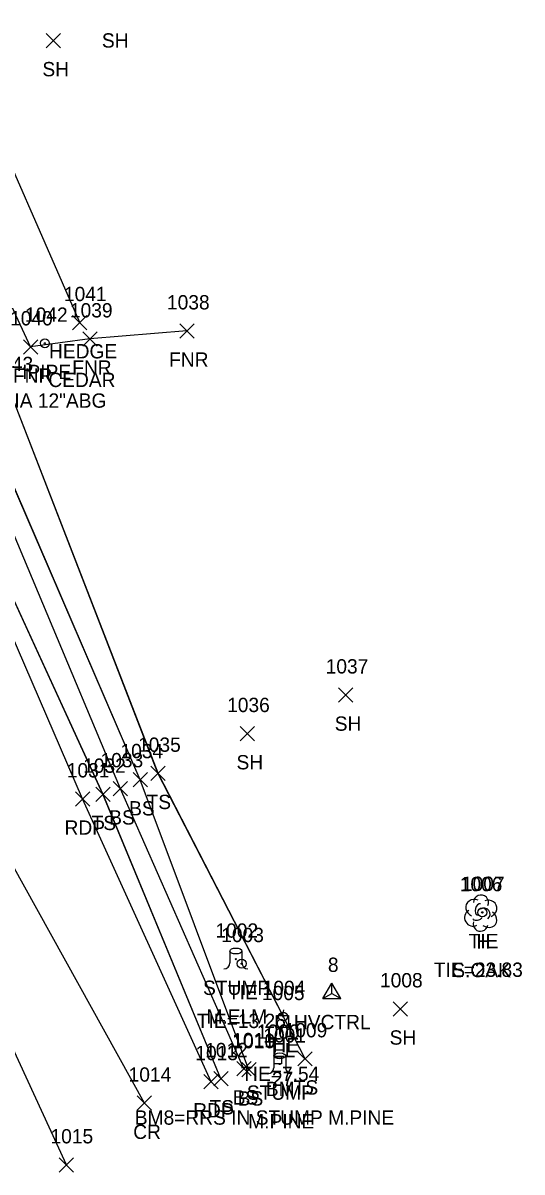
# Model space of a CAD drawing. Extents: x 1415642 to 1422021, y 544543 to 547232.
# Drawn here: x 1416593.3 to 1416662.9, y 546174.1 to 546334.5 of the extents above; entities that cross this region are included whole.
import ezdxf

# ---------------------------------------------------------------- set-up
doc = ezdxf.new("R2010")
doc.units = 0
for name, color, linetype in [('C_A', 7, 'Continuous'), ('C_C', 7, 'Continuous'), ('C_I', 7, 'Continuous'), ('CBP', 7, 'Continuous'), ('CPBM', 7, 'Continuous'), ('CPSM', 7, 'Continuous'), ('L_A', 7, 'Continuous'), ('L_C', 7, 'Continuous'), ('L_I', 7, 'Continuous'), ('L_TIC', 7, 'Continuous'), ('LAHR', 7, 'Continuous'), ('LELB', 7, 'Continuous'), ('LFNC', 7, 'Continuous'), ('LTD', 7, 'Continuous'), ('LTS', 7, 'Continuous'), ('M_A', 7, 'Continuous'), ('M_C', 7, 'Continuous'), ('M_I', 7, 'Continuous'), ('MPIP', 7, 'Continuous'), ('P_A', 7, 'Continuous'), ('P_I', 7, 'Continuous'), ('P_TIC', 7, 'Continuous'), ('PET', 7, 'Continuous'), ('PRC', 7, 'Continuous'), ('U_A', 7, 'Continuous'), ('U_C', 7, 'Continuous'), ('U_I', 7, 'Continuous'), ('UEPT', 7, 'Continuous')]:
    doc.layers.add(name, color=color, linetype=linetype)

msp = doc.modelspace()

# ---------------------------------------------------------------- linework, layer by layer
at = {"layer": 'CBP'}
for centre, radius in [((1416657.4, 546210.31), 0.625), ((1416657.4, 546210.31), 0.0833), ((1416623.82, 546203.16), 0.625), ((1416623.82, 546203.16), 0.0833), ((1416629.6, 546195.77), 0.625), ((1416629.6, 546195.77), 0.0833)]:
    msp.add_circle(centre, radius, dxfattribs=at)
at = {"layer": 'CPBM'}
for p, q in [((1416628.37, 546189.16), (1416628.37, 546190.16)), ((1416628.37, 546190.16), (1416629.37, 546190.16)), ((1416629.37, 546189.16), (1416628.37, 546189.16)), ((1416628.87, 546189.66), (1416628.87, 546189.66)), ((1416628.87, 546189.66), (1416628.87, 546189.66)), ((1416629.37, 546190.16), (1416629.37, 546189.16))]:
    msp.add_line(p, q, dxfattribs=at)
at = {"layer": 'CPSM'}
for p, q in [((1416635.16, 546198.28), (1416636.41, 546200.45)), ((1416637.66, 546198.28), (1416636.41, 546200.45)), ((1416636.41, 546199), (1416636.41, 546200.45)), ((1416635.16, 546198.28), (1416636.41, 546199)), ((1416636.41, 546199), (1416636.41, 546199)), ((1416636.41, 546199), (1416637.66, 546198.28)), ((1416635.16, 546198.28), (1416637.66, 546198.28))]:
    msp.add_line(p, q, dxfattribs=at)
at = {"layer": 'L_TIC'}
for points in [[(1416596.53, 546331.09), (1416598.53, 546333.09)], [(1416598.53, 546331.09), (1416596.53, 546333.09)], [(1416600.24, 546291.69), (1416602.24, 546293.69)], [(1416602.24, 546291.69), (1416600.24, 546293.69)], [(1416601.64, 546289.41), (1416603.64, 546291.41)], [(1416603.64, 546289.41), (1416601.64, 546291.41)], [(1416615.17, 546290.53), (1416617.17, 546292.53)], [(1416617.17, 546290.53), (1416615.17, 546292.53)], [(1416593.37, 546288.3), (1416595.37, 546290.3)], [(1416595.37, 546288.3), (1416593.37, 546290.3)], [(1416637.31, 546239.68), (1416639.31, 546241.68)], [(1416639.31, 546239.68), (1416637.31, 546241.68)], [(1416623.61, 546234.29), (1416625.61, 546236.29)], [(1416625.61, 546234.29), (1416623.61, 546236.29)], [(1416611.14, 546228.74), (1416613.14, 546230.74)], [(1416613.14, 546228.74), (1416611.14, 546230.74)], [(1416608.68, 546227.85), (1416610.68, 546229.85)], [(1416610.68, 546227.85), (1416608.68, 546229.85)], [(1416603.47, 546225.81), (1416605.47, 546227.81)], [(1416605.47, 546225.81), (1416603.47, 546227.81)], [(1416605.9, 546226.58), (1416607.9, 546228.58)], [(1416607.9, 546226.58), (1416605.9, 546228.58)], [(1416644.97, 546195.84), (1416646.97, 546197.84)], [(1416646.97, 546195.84), (1416644.97, 546197.84)], [(1416631.67, 546188.86), (1416633.67, 546190.86)], [(1416633.67, 546188.86), (1416631.67, 546190.86)], [(1416623.13, 546187.48), (1416625.13, 546189.48)], [(1416625.13, 546187.48), (1416623.13, 546189.48)], [(1416623.83, 546187.33), (1416625.83, 546189.33)], [(1416625.83, 546187.33), (1416623.83, 546189.33)], [(1416619.93, 546186.09), (1416621.93, 546188.09)], [(1416621.93, 546186.09), (1416619.93, 546188.09)]]:
    msp.add_lwpolyline(points, dxfattribs=at)
at = {"layer": 'LAHR'}
for points in [[(1416601.24, 546292.69), (1416586.35, 546326.71), (1416573.12, 546362.04), (1416558.49, 546390.29), (1416537.49, 546434.36), (1416523.93, 546467.1), (1416523.32, 546471.61)], [(1416601.24, 546292.69), (1416586.35, 546326.71), (1416573.12, 546362.03), (1416558.49, 546390.29), (1416537.49, 546434.36), (1416523.93, 546467.1), (1416523.32, 546471.61)]]:
    msp.add_lwpolyline(points, dxfattribs=at)
at = {"layer": 'LELB'}
for points in [[(1416624.83, 546188.33), (1416609.68, 546228.85), (1416587.46, 546280.33), (1416569.58, 546317.95), (1416555.08, 546351.62), (1416539.63, 546384.17), (1416546.45, 546386.59), (1416544.38, 546389.65), (1416537.72, 546389.11), (1416521.41, 546422.69), (1416507.02, 546457.32), (1416500.86, 546474.51), (1416499.33, 546475.96), (1416498.77, 546475.76), (1416499.17, 546473.82)], [(1416624.83, 546188.34), (1416609.68, 546228.85), (1416587.45, 546280.34), (1416569.58, 546317.95), (1416555.08, 546351.63), (1416539.63, 546384.17), (1416546.45, 546386.59), (1416544.38, 546389.64), (1416537.72, 546389.12), (1416521.42, 546422.68), (1416507.02, 546457.32), (1416500.87, 546474.51), (1416499.33, 546475.96), (1416498.77, 546475.76), (1416499.17, 546473.83)], [(1416624.13, 546188.48), (1416606.9, 546227.58), (1416585.22, 546279.32), (1416567.76, 546317.19), (1416553.66, 546350.45), (1416534.43, 546386.06), (1416517.2, 546422.02), (1416505.52, 546457.03), (1416499.17, 546473.83)], [(1416624.13, 546188.48), (1416606.9, 546227.58), (1416585.22, 546279.32), (1416567.76, 546317.19), (1416553.66, 546350.45), (1416534.43, 546386.06), (1416517.2, 546422.01), (1416505.52, 546457.03), (1416499.17, 546473.82)], [(1416620.93, 546187.09), (1416604.47, 546226.81), (1416580.95, 546278.02), (1416564.18, 546315.62), (1416549.05, 546348.52), (1416530.53, 546385.22), (1416512.89, 546419.96), (1416490.18, 546459.78)], [(1416620.93, 546187.09), (1416604.48, 546226.8), (1416580.95, 546278.02), (1416564.18, 546315.62), (1416549.05, 546348.51), (1416530.53, 546385.22), (1416512.89, 546419.96), (1416490.18, 546459.78)], [(1416632.67, 546189.86), (1416612.14, 546229.74), (1416591.55, 546282.91), (1416575.19, 546320.43), (1416559.06, 546353.84), (1416543.37, 546383.11), (1416547.74, 546382.96), (1416548.95, 546386.35)], [(1416632.67, 546189.86), (1416612.15, 546229.74), (1416591.55, 546282.91), (1416575.19, 546320.43), (1416559.06, 546353.84), (1416543.37, 546383.11), (1416547.74, 546382.97), (1416548.95, 546386.35)]]:
    msp.add_lwpolyline(points, dxfattribs=at)
at = {"layer": 'LFNC'}
for points in [[(1416616.17, 546291.53), (1416602.64, 546290.41), (1416594.37, 546289.3), (1416578.97, 546322.54), (1416563.77, 546356.27), (1416548.95, 546386.35), (1416547.3, 546389.95), (1416530.29, 546426.68), (1416513.55, 546462.2), (1416508.34, 546472.94), (1416504.48, 546483), (1416512.48, 546489.98)], [(1416616.17, 546291.53), (1416602.64, 546290.41), (1416594.37, 546289.3), (1416578.97, 546322.54), (1416563.77, 546356.27), (1416548.95, 546386.35), (1416547.3, 546389.95), (1416530.29, 546426.68), (1416513.55, 546462.2), (1416508.35, 546472.93), (1416504.48, 546483), (1416512.48, 546489.98)]]:
    msp.add_lwpolyline(points, dxfattribs=at)
at = {"layer": 'LTD'}
msp.add_line((1416657.15, 546210.26), (1416657.15, 546210.26), dxfattribs=at)
msp.add_line((1416657.15, 546210.26), (1416657.15, 546210.26), dxfattribs=at)
msp.add_arc((1416657.2, 546211.69), 1.05, 335.5272, 180.9563, dxfattribs=at)
for centre, major_axis, ratio, start_param, end_param in [((1416656.36, 546210.92), (1.21, -0.51), 0.895232, 1.570796, 4.712389), ((1416656.94, 546210.71), (-0.208, -0.792), 0.645439, 3.141593, 6.283185), ((1416658.19, 546210.84), (-1.14, -0.48), 0.949671, 1.570796, 4.712389), ((1416656.07, 546209.55), (0.58, -1.04), 0.959034, 3.141593, 6.283185), ((1416656.69, 546209.5), (-0.625, -0.083), 0.423636, 0, 3.141593), ((1416657.65, 546210.09), (-0.5, 0.667), 0.989748, 3.141593, 6.283185), ((1416658.15, 546209.42), (-1.09, 0.79), 0.841452, 1.570796, 4.712389), ((1416657.15, 546208.76), (0.26, 1.06), 0.942809, 1.570796, 4.712389)]:
    msp.add_ellipse(centre, major_axis=major_axis, ratio=ratio, start_param=start_param, end_param=end_param, dxfattribs=at)
at = {"layer": 'LTS'}
for p, q in [((1416622.18, 546204.92), (1416622.18, 546203.26)), ((1416623.85, 546204.75), (1416623.85, 546204.92)), ((1416623.85, 546204.92), (1416623.85, 546203.26)), ((1416623.01, 546203.78), (1416623.01, 546203.78)), ((1416623.01, 546203.78), (1416623.01, 546203.78)), ((1416623.01, 546203.76), (1416623.01, 546203.76)), ((1416628.29, 546190.28), (1416628.29, 546188.61)), ((1416629.13, 546189.14), (1416629.13, 546189.14)), ((1416629.13, 546189.14), (1416629.13, 546189.14)), ((1416629.13, 546189.11), (1416629.13, 546189.11)), ((1416629.96, 546190.11), (1416629.96, 546190.28)), ((1416629.96, 546190.28), (1416629.96, 546188.61))]:
    msp.add_line(p, q, dxfattribs=at)
for centre in [(1416623.01, 546203.78), (1416629.13, 546189.14)]:
    msp.add_circle(centre, 0.0833, dxfattribs=at)
for centre, start, end in [((1416621.35, 546203.26), 270, 360), ((1416624.68, 546203.26), 180, 270), ((1416627.46, 546188.61), 270, 360), ((1416630.79, 546188.61), 180, 270)]:
    msp.add_arc(centre, 0.833, start, end, dxfattribs=at)
for centre in [(1416623.01, 546204.92), (1416629.13, 546190.28)]:
    msp.add_ellipse(centre, major_axis=(-0.833, 0), ratio=0.5, dxfattribs=at)
at = {"layer": 'MPIP'}
for radius in [0.625, 0.0833]:
    msp.add_circle((1416596.36, 546289.8), radius, dxfattribs=at)
at = {"layer": 'P_TIC'}
for points in [[(1416600.62, 546225.16), (1416602.62, 546227.16)], [(1416602.62, 546225.16), (1416600.62, 546227.16)], [(1416618.56, 546185.67), (1416620.56, 546187.67)], [(1416620.56, 546185.67), (1416618.56, 546187.67)], [(1416609.25, 546182.67), (1416611.25, 546184.67)], [(1416611.25, 546182.67), (1416609.25, 546184.67)], [(1416598.36, 546174.05), (1416600.36, 546176.05)], [(1416600.36, 546174.05), (1416598.36, 546176.05)]]:
    msp.add_lwpolyline(points, dxfattribs=at)
at = {"layer": 'PET'}
for points in [[(1416619.56, 546186.67), (1416601.63, 546226.16), (1416579.47, 546277.45), (1416562.03, 546315.23), (1416547.08, 546347.32), (1416527.73, 546384.04), (1416509.97, 546418.47), (1416487.43, 546457.37), (1416462.82, 546495.68), (1416435.56, 546537.44), (1416408.53, 546574.62)], [(1416619.56, 546186.67), (1416601.62, 546226.16), (1416579.47, 546277.45), (1416562.03, 546315.23), (1416547.08, 546347.32), (1416527.73, 546384.03), (1416509.97, 546418.46), (1416487.43, 546457.37), (1416462.82, 546495.68), (1416435.56, 546537.44), (1416408.53, 546574.61)], [(1416599.36, 546175.05), (1416589.42, 546196.6), (1416580.61, 546216.08), (1416556.35, 546269.48), (1416540.49, 546305), (1416525.46, 546337.37), (1416506.55, 546374.02), (1416489.16, 546406.45), (1416459.13, 546457.37), (1416438.7, 546488.16), (1416417.68, 546520.98), (1416388.9, 546560.28)], [(1416599.36, 546175.05), (1416589.42, 546196.6), (1416580.62, 546216.08), (1416556.34, 546269.48), (1416540.49, 546305), (1416525.46, 546337.38), (1416506.55, 546374.02), (1416489.16, 546406.45), (1416459.13, 546457.38), (1416438.7, 546488.17), (1416417.68, 546520.98), (1416388.9, 546560.28)]]:
    msp.add_lwpolyline(points, dxfattribs=at)
at = {"layer": 'PRC'}
for points in [[(1416610.25, 546183.67), (1416586.12, 546227.19), (1416567.64, 546274.51), (1416551.19, 546309.95), (1416536.28, 546342.88), (1416517.21, 546379.83), (1416500.09, 546412.89), (1416469.99, 546464.05), (1416448.59, 546494.95), (1416427.64, 546528.31), (1416425.29, 546532.23), (1416399.16, 546568.17)], [(1416610.26, 546183.67), (1416586.11, 546227.19), (1416567.64, 546274.51), (1416551.18, 546309.96), (1416536.27, 546342.88), (1416517.21, 546379.83), (1416500.09, 546412.89), (1416469.99, 546464.05), (1416448.59, 546494.95), (1416427.64, 546528.31), (1416425.29, 546532.24), (1416399.16, 546568.17)]]:
    msp.add_lwpolyline(points, dxfattribs=at)
at = {"layer": 'UEPT'}
for p, q in [((1416629.67, 546196.72), (1416629.5, 546195.89)), ((1416628.67, 546194.22), (1416628.67, 546195.89)), ((1416628.67, 546195.89), (1416630.33, 546195.89)), ((1416630.33, 546195.89), (1416630.33, 546194.22)), ((1416630.33, 546194.22), (1416628.67, 546194.22)), ((1416629.25, 546193.39), (1416629.5, 546194.22)), ((1416629.5, 546195.06), (1416629.5, 546195.06))]:
    msp.add_line(p, q, dxfattribs=at)

# ---------------------------------------------------------------- texts
at = {"layer": 'C_A'}
for s, p in [('TIE', (1416655.48, 546205.31)), ('TIE', (1416621.9, 546198.16)), ('HVCTRL', (1416631.11, 546194)), ('TIE', (1416627.68, 546190.77)), ('BM', (1416627.19, 546184.66))]:
    msp.add_text(s, height=2, dxfattribs=at).set_placement(p)
at = {"layer": 'C_C'}
for s, p in [('TIE=23.83', (1416650.63, 546201.31)), ('TIE=13.26', (1416617.56, 546194.16)), ('TIE=7.54', (1416623.72, 546186.77)), ('BM8=RRS IN STUMP M.PINE', (1416608.91, 546180.66))]:
    msp.add_text(s, height=2, dxfattribs=at).set_placement(p)
at = {"layer": 'C_I'}
for s, p in [('1007', (1416654.55, 546213.31)), ('1003', (1416620.97, 546206.16)), ('8', (1416635.85, 546202)), ('1004', (1416626.75, 546198.77)), ('1000', (1416625.94, 546192.66))]:
    msp.add_text(s, height=2, dxfattribs=at).set_placement(p)
at = {"layer": 'L_A'}
for s, p in [('SH', (1416604.32, 546331.1)), ('SH', (1416596.02, 546327.09)), ('HEDGE', (1416596.94, 546287.69)), ('FNR', (1416613.7, 546286.53)), ('FNR', (1416600.18, 546285.41)), ('FNR', (1416591.91, 546284.3)), ('SH', (1416636.8, 546235.68)), ('SH', (1416623.1, 546230.29)), ('BS', (1416608.12, 546223.85)), ('TS', (1416610.55, 546224.74)), ('BS', (1416605.34, 546222.58)), ('TS', (1416602.88, 546221.81)), ('H', (1416656.58, 546205.26)), ('STUMP', (1416618.43, 546198.78)), ('SH', (1416644.46, 546191.84)), ('BS', (1416622.57, 546183.48)), ('STUMP', (1416624.55, 546184.14)), ('TS', (1416631.08, 546184.86)), ('TS', (1416619.34, 546182.09)), ('BS', (1416623.27, 546183.33))]:
    msp.add_text(s, height=2, dxfattribs=at).set_placement(p)
at = {"layer": 'L_C'}
for s, p in [('CEDAR', (1416596.85, 546283.69)), ('S.OAK', (1416653.2, 546201.26)), ('M.ELM', (1416618.91, 546194.78)), ('M.PINE', (1416624.73, 546180.14))]:
    msp.add_text(s, height=2, dxfattribs=at).set_placement(p)
at = {"layer": 'L_I'}
for s, p in [('1041', (1416599.03, 546295.69)), ('1038', (1416613.4, 546294.53)), ('1039', (1416599.86, 546293.41)), ('1040', (1416591.51, 546292.3)), ('1043', (1416588.78, 546285.91)), ('1037', (1416635.54, 546243.68)), ('1036', (1416621.79, 546238.29)), ('1034', (1416606.91, 546231.85)), ('1035', (1416609.37, 546232.74)), ('1033', (1416604.13, 546230.58)), ('1032', (1416601.7, 546229.81)), ('1006', (1416654.24, 546213.26)), ('1002', (1416620.16, 546206.78)), ('1008', (1416643.12, 546199.84)), ('1011', (1416622.5, 546191.48)), ('1001', (1416626.84, 546192.14)), ('1009', (1416629.81, 546192.86)), ('1012', (1416618.72, 546190.09)), ('1010', (1416622.54, 546191.33))]:
    msp.add_text(s, height=2, dxfattribs=at).set_placement(p)
at = {"layer": 'M_A'}
msp.add_text('IPIPE', height=2, dxfattribs=at).set_placement((1416593.19, 546284.8))
at = {"layer": 'M_C'}
msp.add_text('2" DIA 12"ABG', height=2, dxfattribs=at).set_placement((1416587, 546280.8))
at = {"layer": 'M_I'}
msp.add_text('1042', height=2, dxfattribs=at).set_placement((1416593.59, 546292.8))
at = {"layer": 'P_A'}
for s, p in [('RDP', (1416599.11, 546221.16)), ('RDP', (1416617.05, 546181.67)), ('CR', (1416608.69, 546178.67))]:
    msp.add_text(s, height=2, dxfattribs=at).set_placement(p)
at = {"layer": 'P_I'}
for s, p in [('1031', (1416599.42, 546229.16)), ('1013', (1416617.36, 546189.67)), ('1014', (1416608.05, 546186.67)), ('1015', (1416597.15, 546178.05))]:
    msp.add_text(s, height=2, dxfattribs=at).set_placement(p)
at = {"layer": 'U_A'}
msp.add_text('EL', height=2, dxfattribs=at).set_placement((1416628.04, 546190.06))
at = {"layer": 'U_C'}
msp.add_text('27', height=2, dxfattribs=at).set_placement((1416628.04, 546186.06))
at = {"layer": 'U_I'}
msp.add_text('1005', height=2, dxfattribs=at).set_placement((1416626.65, 546198.06))

doc.saveas('drawing.dxf')
